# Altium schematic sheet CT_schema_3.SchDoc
size 368 x 309 mm
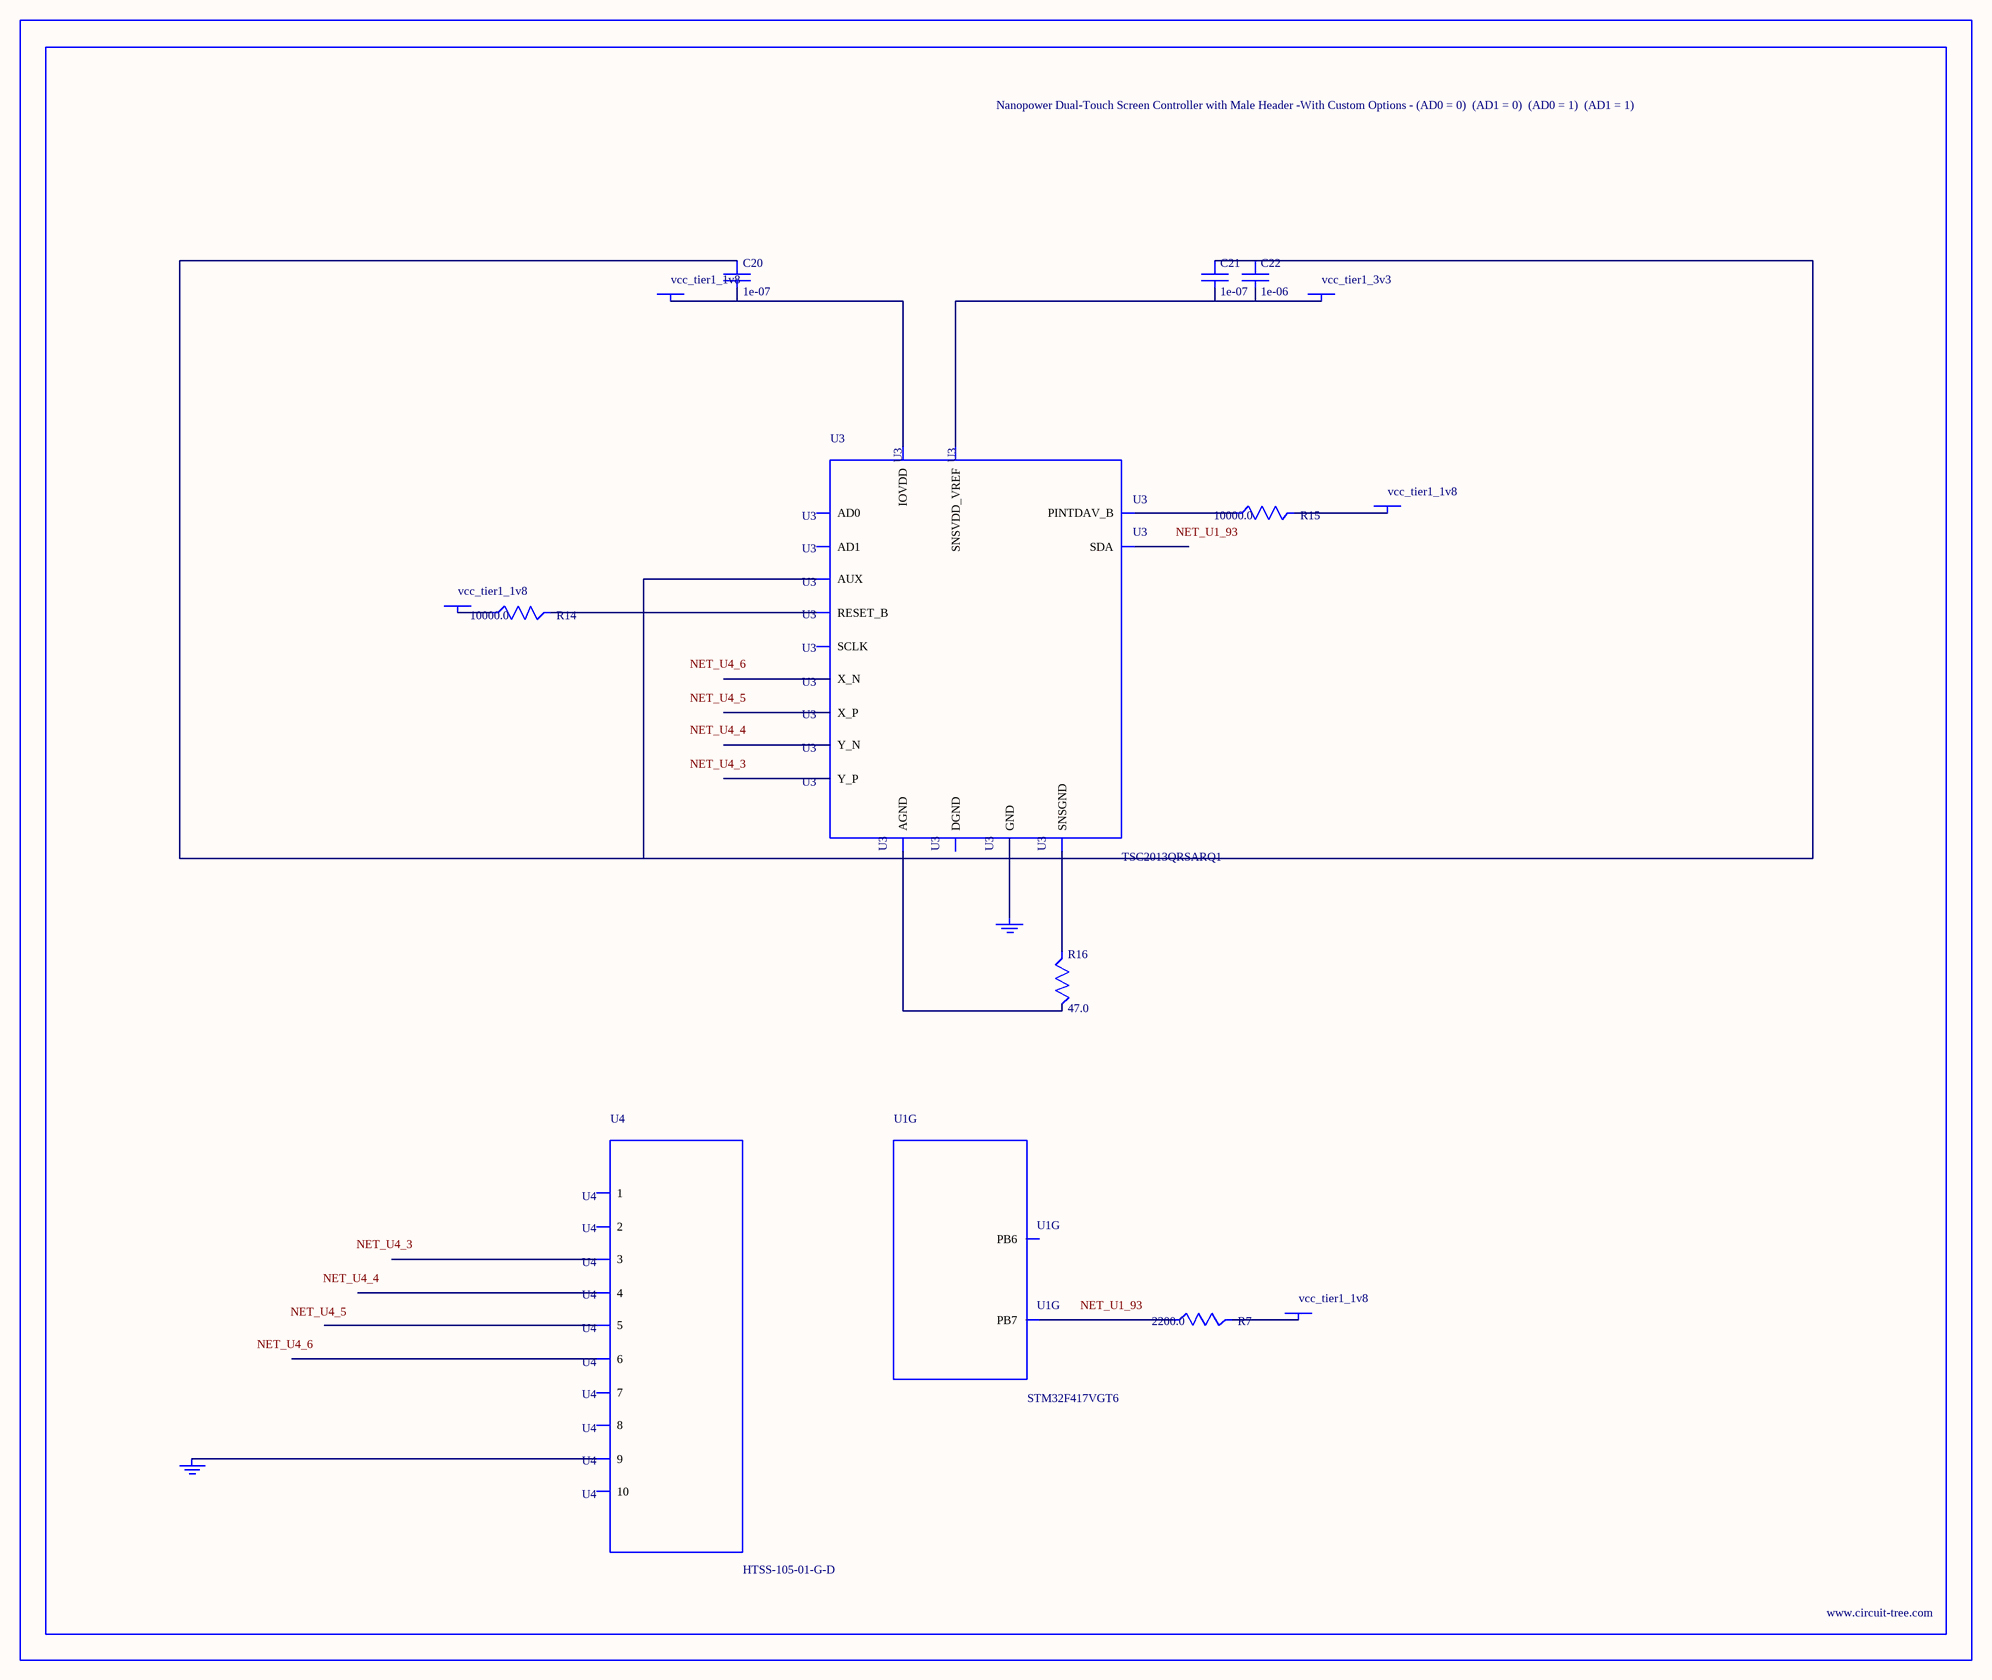
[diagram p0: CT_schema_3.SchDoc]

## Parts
BORDER2  (no value)
C20  1e-07  [C0402]
C21  1e-07  [C0402]
C22  1e-06  [C0603]
GND_INSTANCE_2_0  (no value)
GND_INSTANCE_2_1  (no value)
POWER_INSTANCE_2_0  vcc_tier1_1v8
POWER_INSTANCE_2_1  vcc_tier1_1v8
POWER_INSTANCE_2_2  vcc_tier1_1v8
POWER_INSTANCE_2_3  vcc_tier1_3v3
POWER_INSTANCE_2_4  vcc_tier1_1v8
R7  2200.0  [R0603]
R14  10000.0  [R0603]
R15  10000.0  [R0603]
R16  47.0  [R0603]
U1  STM32F417VGT6  [LQFP100]  (part G of 8)
U3  TSC2013QRSARQ1  [QFN65P400X400X100-17N]
U4  HTSS-105-01-G-D  [HTSS-105-01-G-D]

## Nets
NetC20_1: C20.1 C21.1 C22.1 R16.1 R16.2 U3.8(AUX) U3.9(AGND) U3.15(SNSGND)
NetC20_2: C20.2 POWER_INSTANCE_2_2.0(PWR) U3.7(IOVDD)
NetC21_2: C21.2 C22.2 POWER_INSTANCE_2_3.0(PWR) U3.10(SNSVDD_VREF)
NetGND_INSTANCE_2_0_0: GND_INSTANCE_2_0.0(GND) U3.17(GND)
NetGND_INSTANCE_2_1_0: GND_INSTANCE_2_1.0(GND) U4.9
NetPOWER_INSTANCE_2_0_0: POWER_INSTANCE_2_0.0(PWR) R15.2
NetPOWER_INSTANCE_2_1_0: POWER_INSTANCE_2_1.0(PWR) R14.1
NetPOWER_INSTANCE_2_4_0: POWER_INSTANCE_2_4.0(PWR) R7.2
NetR7_1: R7.1 U1.93(PB7)
NetR14_2: R14.2 U3.5(RESET_B)
NetR15_1: R15.1 U3.4(PINTDAV_B)

Not connected (* = marked no-connect by the designer): U1 92(PB6); U3 1(SDA) 2(SCLK) 3(AD1) 6(DGND) 11(X_P) 12(Y_P) 13(X_N) 14(Y_N) 16(AD0); U4 1 2 3 4 5 6 7 8 10

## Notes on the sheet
- Labels drawn without touching a wire or pin: NET_U1_93, NET_U4_3, NET_U4_4, NET_U4_5, NET_U4_6

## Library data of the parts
BORDER2 = BORDER_PAGE2
C20 C21 = C0402C104K3RACTU
C22 = C0603C105K3RACTU
GND_INSTANCE_2_0 GND_INSTANCE_2_1 = GND
POWER_INSTANCE_2_0-POWER_INSTANCE_2_4 = PWR
R7 = RC0603JR-072K2L
R14 R15 = RC0603JR-0710KL
R16 = RC0603JR-0747RL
